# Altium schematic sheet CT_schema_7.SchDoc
size 251 x 159 mm
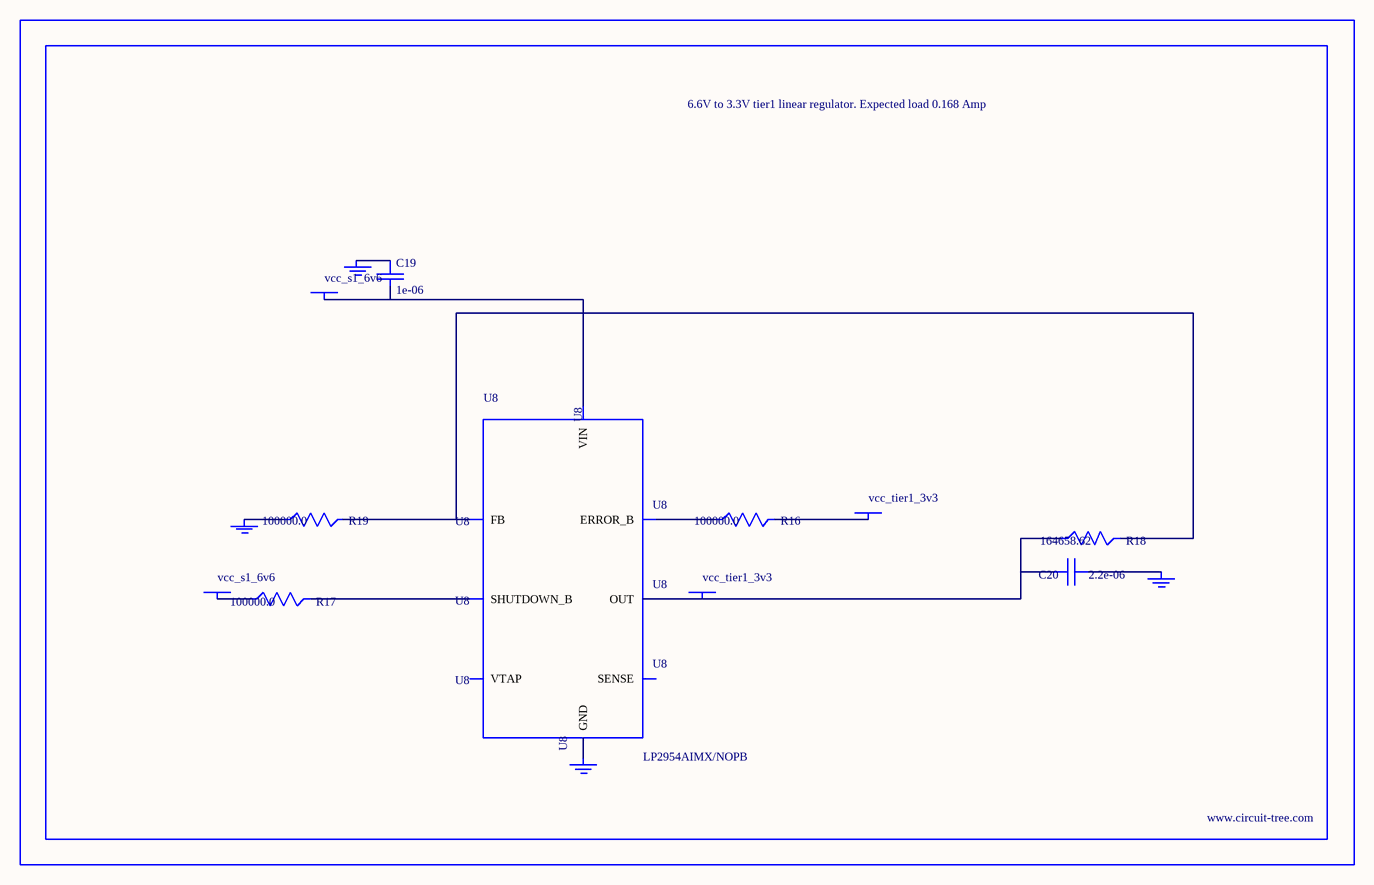
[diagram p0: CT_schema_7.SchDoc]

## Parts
BORDER6  (no value)
C19  1e-06  [EXV-9B]
C20  2.2e-06  [EXV-9B]
GND_INSTANCE_6_0  (no value)
GND_INSTANCE_6_1  (no value)
GND_INSTANCE_6_2  (no value)
GND_INSTANCE_6_3  (no value)
POWER_INSTANCE_6_0  vcc_s1_6v6
POWER_INSTANCE_6_1  vcc_tier1_3v3
POWER_INSTANCE_6_2  vcc_s1_6v6
POWER_INSTANCE_6_3  vcc_tier1_3v3
R16  100000.0  [R0603]
R17  100000.0  [R0603]
R18  164658.62  [R0603]
R19  100000.0  [R0603]
U8  LP2954AIMX/NOPB  [LP2954]

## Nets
NetC19_1: C19.1 GND_INSTANCE_6_2.0(GND)
NetC19_2: C19.2 POWER_INSTANCE_6_2.0(PWR) U8.8(VIN)
NetC20_1: C20.1 GND_INSTANCE_6_0.0(GND)
NetC20_2: C20.2 POWER_INSTANCE_6_3.0(PWR) R18.1 U8.1(OUT)
NetGND_INSTANCE_6_1_0: GND_INSTANCE_6_1.0(GND) R19.1
NetGND_INSTANCE_6_3_0: GND_INSTANCE_6_3.0(GND) U8.4(GND)
NetPOWER_INSTANCE_6_0_0: POWER_INSTANCE_6_0.0(PWR) R17.1
NetPOWER_INSTANCE_6_1_0: POWER_INSTANCE_6_1.0(PWR) R16.2
NetR16_1: R16.1 U8.5(ERROR_B)
NetR17_2: R17.2 U8.3(SHUTDOWN_B)
NetR18_2: R18.2 R19.2 U8.7(FB)

Not connected (* = marked no-connect by the designer): U8 2(SENSE) 6(VTAP)

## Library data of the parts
BORDER6 = BORDER_PAGE6
C19 = EDK105M050A9BAA
C20 = EDK225M050A9BAA
GND_INSTANCE_6_0-GND_INSTANCE_6_3 = GND
POWER_INSTANCE_6_0-POWER_INSTANCE_6_3 = PWR
R16 R17 R19 = RC0603JR-07100KL
R18 = R18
